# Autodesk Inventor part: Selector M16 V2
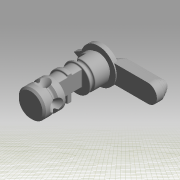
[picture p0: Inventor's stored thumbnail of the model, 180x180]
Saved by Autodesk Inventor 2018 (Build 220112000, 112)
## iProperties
Created: 2019-01
Part Number: Selector M16 V2
Material: Generic
Document SubType Name: Modeling
Designer: johne
Appearance: Default
Author: johne
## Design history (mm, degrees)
feature "Solid2"
feature "Solid3"
body "Solid1"
body "Solid4"
